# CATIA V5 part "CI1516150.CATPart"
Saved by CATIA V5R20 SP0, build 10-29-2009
Part number: CI1516150
Bounding box of the stored display mesh (mm): x -15 to 15, y -11.584 to 174, z -18.579 to 17.128
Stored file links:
  C:\Users\Raffaele\Desktop\3D X SITO CF\BOLEX\19-INCLINED ASSEMBLY REF_CI\CI1516150.CATPart

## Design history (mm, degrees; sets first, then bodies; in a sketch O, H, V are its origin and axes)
Set1
  DatumSurface1 to DatumSurface16 "MANIFOLD_SOLID_BREP #385"
  DatumSurface17 to DatumSurface39 "MANIFOLD_SOLID_BREP #1110"
Body1 (main body)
